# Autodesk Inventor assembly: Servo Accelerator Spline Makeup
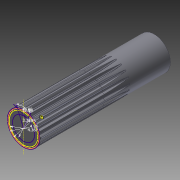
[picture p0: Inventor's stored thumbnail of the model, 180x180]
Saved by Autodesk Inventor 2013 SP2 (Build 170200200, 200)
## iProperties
Created: 2020-02
Part Number: Servo Accelerator Spline Makeup
Document SubType Name: Assembly
Designer: DELL
Author: DELL
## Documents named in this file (3)
- C:\Users\DELL\Dropbox\Inventor\Projects\Quadcopter F450\Assemblies\Servo - Design Accelerator Spline Tutorial\Servo - Design Accelerator Spline Tutorial.iam
- C:\Users\DELL\Dropbox\Inventor\Projects\Quadcopter F450\Assemblies\Servo - Design Accelerator Spline Tutorial\5mm Shaft - Spline Tutorial.ipt
- C:\Users\DELL\Dropbox\Inventor\Projects\Quadcopter F450\Assemblies\Servo - Design Accelerator Spline Tutorial\Design Accelerator\Involute Spline Connection2.iam
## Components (2 placed, 2 different names)
1. Shaft Test:1
2. Involute Spline Connection:1 [sub-assembly]
